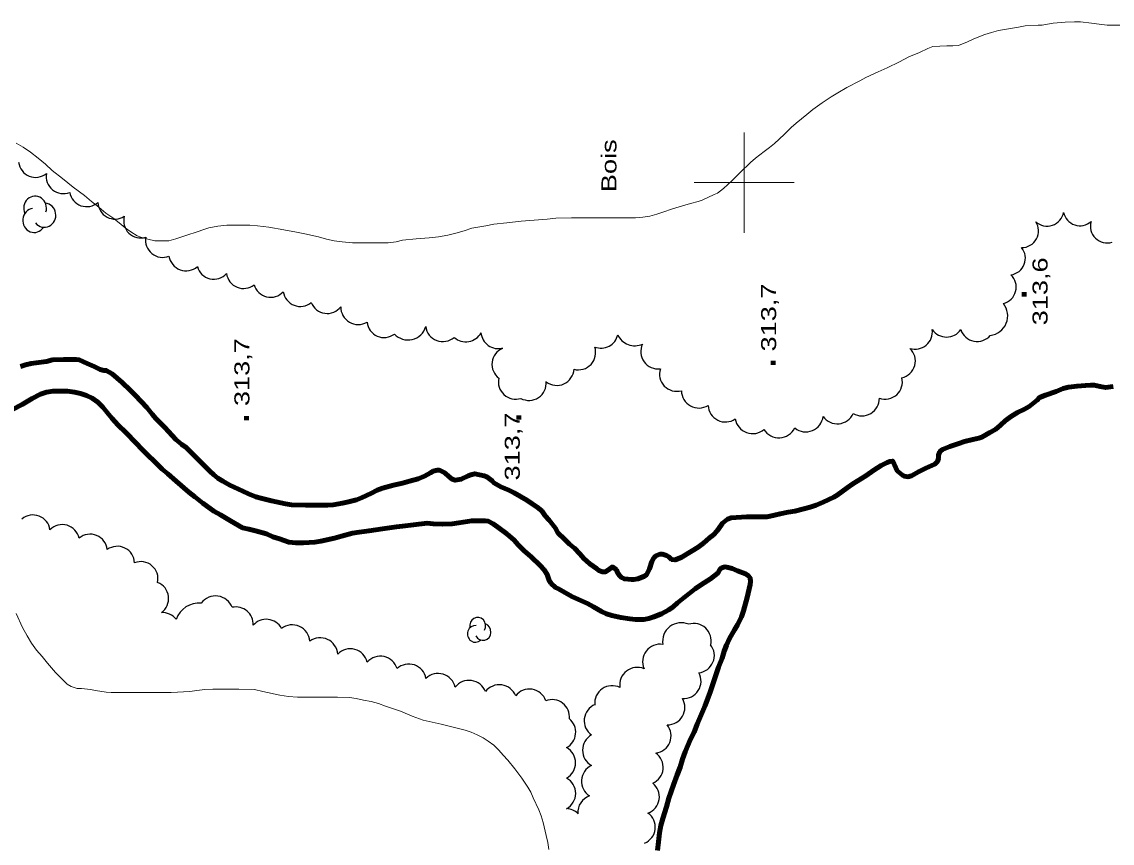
# Model space of a CAD drawing. Extents: x 240591 to 242335, y 5323482 to 5326937.
# Drawn here: x 241255.7 to 241473.5, y 5324068.1 to 5324232.1 of the extents above; entities that cross this region are included whole.
import ezdxf
from ezdxf.enums import TextEntityAlignment as Align

# ---------------------------------------------------------------- set-up
doc = ezdxf.new("R2010")
doc.units = 0
doc.header["$LTSCALE"] = 1.2
doc.linetypes.add('DASH_DOUBLE_DOT', pattern=[9.2, 5, -1.2, 0.3, -1.2, 0.3, -1.2])
doc.linetypes.add('LONG_DASHED', pattern=[7.5, 6, -1.5])
for name, color, linetype, lineweight in [('2', 7, 'Continuous', 13), ('3', 7, 'Continuous', 140), ('4', 7, 'DASH_DOUBLE_DOT', 53), ('44', 7, 'Continuous', 25), ('61', 7, 'Continuous', 13)]:
    doc.layers.add(name, color=color, linetype=linetype, lineweight=lineweight)

msp = doc.modelspace()

# ---------------------------------------------------------------- linework, layer by layer
at = {"layer": '2', "linetype": 'LONG_DASHED'}
for points in [[(241458.7, 5324231.4), (241456.1, 5324231.3), (241454.8, 5324231), (241452.4, 5324230.6), (241450.8, 5324230.4), (241449.4, 5324230), (241448.1, 5324229.6), (241445.9, 5324228.7), (241444.6, 5324228.1), (241442.8, 5324227.4), (241441.7, 5324227.3), (241440.5, 5324227.3), (241437.7, 5324227.2), (241436.7, 5324226.8), (241435, 5324226), (241432.9, 5324225.1), (241431, 5324224.1), (241428.6, 5324222.9), (241426.8, 5324222.1), (241424.3, 5324221), (241423.1, 5324220.3), (241420.5, 5324219), (241418.7, 5324217.9), (241417.4, 5324217.1), (241415.6, 5324215.9), (241413.7, 5324214.6), (241412.5, 5324213.6), (241410.4, 5324211.9), (241409.4, 5324211), (241408, 5324209.6), (241406.1, 5324207.8), (241405.1, 5324207), (241404, 5324206.2), (241402.3, 5324204.9), (241401.3, 5324204), (241399.2, 5324202), (241397.6, 5324200.4), (241395.9, 5324198.8), (241394.7, 5324197.9), (241394, 5324197.6), (241391.6, 5324196.5), (241390.8, 5324196.2), (241389.3, 5324195.8), (241387, 5324195.2), (241385.5, 5324194.7), (241384, 5324194.2), (241382.6, 5324193.7), (241381.2, 5324193.3), (241379.8, 5324193.1), (241378.3, 5324193), (241376.6, 5324193), (241373.7, 5324193), (241370.9, 5324193), (241368.1, 5324193), (241365.5, 5324193), (241362.4, 5324192.9), (241360.7, 5324192.7), (241358.1, 5324192.5), (241355.5, 5324192.3), (241352.6, 5324192), (241350, 5324191.7), (241348.4, 5324191.4), (241345.6, 5324190.9), (241344.1, 5324190.4), (241342.4, 5324189.9), (241340.8, 5324189.5), (241339, 5324189.2), (241337.1, 5324189), (241334.5, 5324188.8), (241331.8, 5324188.5), (241330.5, 5324188.2), (241328.9, 5324188), (241326.9, 5324188), (241324.3, 5324188), (241321.8, 5324188), (241319.7, 5324188.2), (241318.1, 5324188.4), (241316.6, 5324188.7), (241315, 5324189.2), (241312.3, 5324189.8), (241310.6, 5324190.1), (241308.1, 5324190.6), (241305.1, 5324191.1), (241302.8, 5324191.4), (241301.3, 5324191.5), (241299.8, 5324191.5), (241296.7, 5324191.5), (241294.9, 5324191.3), (241293.1, 5324191), (241292.3, 5324190.7), (241290.6, 5324190.1), (241288.9, 5324189.6), (241286.5, 5324188.8), (241285.1, 5324188.4), (241284.4, 5324188.4), (241282.3, 5324188.4), (241280.9, 5324188.7), (241279.5, 5324189.1), (241278.8, 5324189.4), (241277.5, 5324190.2), (241276.4, 5324191)], [(241276.4, 5324191), (241275.2, 5324192), (241273.9, 5324193), (241272.5, 5324193.9), (241271.1, 5324195.1), (241269.7, 5324196.2), (241268.3, 5324197.4), (241266, 5324199.1), (241263.9, 5324200.8), (241261.8, 5324202.4), (241260.5, 5324203.7), (241259, 5324204.9), (241257.5, 5324206.1), (241256, 5324207.1), (241254.6, 5324207.9)], [(241254.6, 5324114), (241255.9, 5324111.2), (241256.8, 5324109.5), (241257.7, 5324108.1), (241258.7, 5324106.7), (241259.8, 5324105.4), (241260.9, 5324104.1), (241262.5, 5324102.2), (241263.7, 5324101), (241264.8, 5324099.9), (241265.6, 5324099.4)], [(241265.6, 5324099.4), (241266.8, 5324099), (241267.7, 5324099), (241269.5, 5324098.8), (241270.5, 5324098.6), (241272.6, 5324098.3), (241273.6, 5324098.2), (241275.7, 5324098.2), (241278.8, 5324098.2), (241282.3, 5324098.2), (241285.6, 5324098.2), (241289.3, 5324098.4), (241290.7, 5324098.6), (241292.3, 5324098.8), (241293.9, 5324098.9), (241295.7, 5324098.9), (241299.1, 5324098.9), (241302.2, 5324098.8), (241303.9, 5324098.4), (241307.3, 5324097.7), (241309, 5324097.4), (241310.8, 5324097.3), (241312.5, 5324097.3), (241315.3, 5324097.3), (241318.8, 5324097.3), (241321.2, 5324097.2), (241322.5, 5324097), (241324, 5324096.7), (241325.5, 5324096.4), (241327, 5324096), (241328.4, 5324095.5), (241330.8, 5324094.7), (241331.4, 5324094.5), (241333.7, 5324093.5), (241335.9, 5324092.7), (241337.1, 5324092.4), (241339.5, 5324091.9), (241341.9, 5324091.3), (241344.3, 5324090.7), (241345.5, 5324090.3), (241346.7, 5324089.8), (241347.9, 5324089.2), (241348.9, 5324088.5), (241350, 5324087.7), (241351, 5324086.7), (241351.9, 5324085.7), (241352.8, 5324084.7), (241354.2, 5324083), (241355.6, 5324081.1), (241356.8, 5324079.3), (241357.4, 5324078.3), (241357.9, 5324077.2), (241359, 5324074.8), (241359.5, 5324073.6), (241359.9, 5324072.3), (241360.5, 5324069.7), (241360.8, 5324068.3), (241361, 5324066.9)]]:
    msp.add_lwpolyline(points, dxfattribs=at)
at = {"layer": '2'}
msp.add_lwpolyline([(241475.6, 5324231.4), (241472.5, 5324231.4), (241470.9, 5324231.6), (241469.4, 5324231.8), (241467.2, 5324232.1), (241466, 5324232.1), (241464.1, 5324232), (241461.7, 5324231.8), (241460.6, 5324231.6), (241459.5, 5324231.4), (241458.7, 5324231.4)], dxfattribs=at)
at = {"layer": '3'}
for p, q in [((241455.9, 5324177.3), (241455.9, 5324178.1)), ((241405.8, 5324163.6), (241405.8, 5324164.4)), ((241300.6, 5324152.6), (241300.6, 5324153.4)), ((241355, 5324152.7), (241355, 5324153.5))]:
    msp.add_line(p, q, dxfattribs=at)
at = {"layer": '4', "linetype": 'Continuous', "lineweight": 90}
for points in [[(241280.7, 5324155.1), (241279.6, 5324156.3), (241278.4, 5324157.6), (241277.4, 5324158.6), (241275.8, 5324160.1), (241273.8, 5324161.8), (241272.6, 5324162.5), (241272.1, 5324162.5), (241271.4, 5324162.7), (241270.2, 5324163.3), (241268.8, 5324163.9), (241267.2, 5324164.6), (241266.6, 5324164.7), (241264.1, 5324164.7), (241261.9, 5324164.6), (241260.7, 5324164.3), (241258.6, 5324164), (241257.6, 5324163.9), (241256.5, 5324163.6), (241255.5, 5324163.3)], [(241253.9, 5324154.7), (241255.8, 5324155.7), (241257.8, 5324156.9), (241259.5, 5324157.8), (241260.7, 5324158.2), (241262, 5324158.4), (241263.4, 5324158.4), (241264.9, 5324158.4), (241266.3, 5324158.2), (241267.5, 5324157.9), (241268.7, 5324157.5), (241269.8, 5324157), (241270.9, 5324156.2), (241271.9, 5324155.2), (241272.8, 5324154.1), (241273.7, 5324153), (241275, 5324151.6), (241276.5, 5324150.1), (241278.6, 5324148), (241279.7, 5324146.8), (241280.8, 5324145.7), (241282.4, 5324144.2), (241283.8, 5324142.8), (241284.9, 5324141.9), (241286.6, 5324140.4), (241289.1, 5324138.2), (241290.3, 5324137.3), (241291.9, 5324136), (241294.1, 5324134.4), (241295.4, 5324133.7), (241297.4, 5324132.5), (241299.8, 5324131.1), (241301.1, 5324130.8), (241302.4, 5324130.5), (241304.6, 5324129.9), (241305.9, 5324129.3), (241307.2, 5324128.9), (241309.1, 5324128.2), (241310.5, 5324128.1), (241312, 5324128.1), (241314.3, 5324128.2), (241315.5, 5324128.4), (241318.2, 5324129), (241319.6, 5324129.4), (241321.8, 5324130), (241323.1, 5324130.2), (241325.1, 5324130.5), (241327.8, 5324130.9), (241330.6, 5324131.3), (241331.8, 5324131.4), (241334, 5324131.7), (241336.7, 5324132), (241337.9, 5324131.9), (241339.8, 5324131.8), (241341.7, 5324131.9), (241343, 5324132.1), (241345.6, 5324132.5), (241346.7, 5324132.5), (241348.3, 5324132.5), (241348.9, 5324132.4), (241349.9, 5324131.9), (241350.8, 5324131.2), (241352.6, 5324129.9), (241354.1, 5324128.6), (241354.9, 5324127.7), (241356.1, 5324126.5), (241357.5, 5324125.3), (241359.3, 5324123.6), (241360.1, 5324122.7), (241360.7, 5324121.8), (241361.1, 5324120.6), (241361.5, 5324120)], [(241473.7, 5324159.3), (241472.2, 5324159.1), (241471.1, 5324159.3), (241469.9, 5324159.6), (241469.2, 5324159.6), (241468.2, 5324159.5), (241466.5, 5324159.4), (241464.8, 5324159.2), (241463.7, 5324158.9), (241462.3, 5324158.3), (241460.2, 5324157.6), (241459, 5324157.1), (241458.5, 5324156.6), (241456.9, 5324155.3), (241456, 5324154.8), (241454.6, 5324154.1), (241453.4, 5324153.4), (241452.2, 5324152.5), (241451.2, 5324151.6), (241450.2, 5324150.7), (241449.1, 5324150.1), (241447.5, 5324149.2), (241446.9, 5324149), (241445.7, 5324148.7), (241444, 5324148.3), (241442.9, 5324147.9), (241441.1, 5324147.3), (241439.6, 5324146.7), (241439.1, 5324146.3), (241438.8, 5324145.6), (241438.8, 5324144.9), (241438.6, 5324144.3), (241438.1, 5324143.8), (241437.5, 5324143.5), (241436.3, 5324143), (241434.8, 5324142.3), (241433.4, 5324141.5), (241432.7, 5324141.3), (241432, 5324141.4), (241431.6, 5324141.6), (241430.6, 5324142.5), (241430.3, 5324143.1), (241429.7, 5324144.4), (241429.1, 5324144.3), (241428.6, 5324144.1), (241427.4, 5324143.5), (241425.9, 5324142.6), (241424.3, 5324141.5), (241421.7, 5324139.9), (241420.6, 5324139.1), (241418.6, 5324137.6), (241417.9, 5324137.2), (241415.8, 5324136.2), (241414.4, 5324135.6), (241413.2, 5324135.2), (241411.9, 5324134.9), (241410.1, 5324134.4), (241408.8, 5324134.2), (241407.2, 5324133.9), (241406.1, 5324133.6), (241404.6, 5324133.3), (241403.5, 5324133.3), (241400.5, 5324133.3), (241397.4, 5324133.1), (241396.7, 5324132.8), (241395.7, 5324132), (241395.4, 5324131.6), (241394.6, 5324130.5), (241393.9, 5324129.7), (241393.1, 5324129.1), (241391.9, 5324128)], [(241391.9, 5324128), (241390.8, 5324127.2), (241389.6, 5324126.5), (241387.4, 5324125.2), (241386.2, 5324124.7), (241385.5, 5324124.8), (241385, 5324125.3), (241384.5, 5324125.6), (241383.7, 5324125.8), (241383.2, 5324125.8), (241382.4, 5324125.5), (241382, 5324125.1), (241381.6, 5324124.4), (241381.1, 5324122.9), (241380.5, 5324121.7), (241380, 5324121.4), (241378.8, 5324120.9), (241378, 5324120.8), (241377.5, 5324120.8), (241376.1, 5324120.9), (241375.5, 5324121.2), (241375.1, 5324121.6), (241374.7, 5324122.2), (241374.5, 5324122.7), (241373.7, 5324123.3), (241373.2, 5324122.9), (241372.3, 5324122.3), (241371.7, 5324122.3), (241371, 5324122.6), (241370.5, 5324123), (241369.2, 5324123.9), (241368, 5324125), (241367.2, 5324125.9), (241366.1, 5324127), (241365.1, 5324127.8), (241364.1, 5324128.8), (241362.8, 5324130.1), (241362.3, 5324131), (241361.1, 5324132.6), (241360.3, 5324133.5), (241359.6, 5324134.5), (241358.7, 5324135.2), (241357.7, 5324135.9), (241356.6, 5324136.6), (241354.1, 5324138.1), (241353, 5324138.6), (241351.4, 5324139.3), (241350, 5324140.1), (241349.7, 5324140.5), (241348.6, 5324141.3), (241348.1, 5324141.5), (241346.2, 5324141.9), (241345.4, 5324141.7), (241344.9, 5324141.5), (241343.5, 5324140.8), (241342.3, 5324140.6), (241341.7, 5324140.8), (241341.1, 5324141.3), (241340.2, 5324142.1), (241339.2, 5324142.6), (241338.7, 5324142.6), (241337.9, 5324142.4), (241337.4, 5324142.1), (241336.2, 5324141.4), (241334.9, 5324140.9), (241333.2, 5324140.4), (241331.8, 5324140), (241330, 5324139.6), (241327.8, 5324139), (241326.7, 5324138.6), (241325.6, 5324138), (241323.6, 5324137.1), (241322.6, 5324136.7), (241321, 5324136.3), (241319.8, 5324136), (241317.9, 5324135.7), (241316.8, 5324135.6), (241315, 5324135.6), (241312.4, 5324135.6), (241309.6, 5324135.7), (241308.4, 5324135.9), (241305.6, 5324136.5), (241303.5, 5324137), (241302.5, 5324137.3), (241301, 5324137.9), (241299.9, 5324138.4), (241297.3, 5324139.6), (241295.9, 5324140.4), (241294.9, 5324141), (241294.1, 5324141.7), (241293.3, 5324142.4), (241291.4, 5324144.3), (241289.9, 5324145.8), (241288.6, 5324147.1), (241287.7, 5324147.7), (241286.5, 5324148.7), (241285.8, 5324149.5), (241284.3, 5324151.1), (241282.5, 5324152.9), (241281.8, 5324153.8), (241280.7, 5324155.1)], [(241361.5, 5324120), (241362.3, 5324119.2), (241362.9, 5324118.9), (241365.6, 5324117.4), (241366.9, 5324116.8), (241368.7, 5324116), (241369.9, 5324115.3), (241371.5, 5324114.4), (241372.5, 5324113.9), (241373.6, 5324113.6), (241375.4, 5324113.2), (241377.2, 5324112.9), (241378.3, 5324112.8), (241380, 5324112.8), (241381, 5324113), (241382, 5324113.3), (241383.5, 5324113.9), (241385, 5324114.7), (241385.8, 5324115.3), (241386.7, 5324116.1), (241388, 5324117.2), (241390.2, 5324118.9), (241391.5, 5324119.8), (241393.3, 5324120.9), (241394.8, 5324122.1), (241395.1, 5324122.7), (241395.5, 5324123.1), (241396.2, 5324123.3), (241396.8, 5324123.2), (241397.6, 5324123), (241398.7, 5324122.5), (241400.3, 5324121.9), (241400.9, 5324121.5), (241401.2, 5324121.1), (241401.3, 5324120.4), (241401.2, 5324119.8), (241400.6, 5324117.2), (241399.9, 5324114.5), (241399.5, 5324113.3), (241398.7, 5324111.7), (241398.1, 5324110.7), (241397.1, 5324109), (241396.5, 5324107.7), (241396, 5324106.5), (241395.6, 5324105.1), (241394.9, 5324103.3), (241394.2, 5324101.3), (241393.2, 5324098.3), (241392.2, 5324095.6), (241391.6, 5324094.2), (241390.6, 5324091.9), (241390, 5324090.3), (241389.3, 5324088.9), (241388.2, 5324086.4), (241387.7, 5324084.9), (241387.2, 5324083.3), (241386.6, 5324081.8), (241385.9, 5324079.8), (241385, 5324077.1), (241384.5, 5324075.4), (241383.8, 5324073.1), (241383.4, 5324071.7), (241383.1, 5324070.2), (241382.9, 5324068.4), (241382.7, 5324066.7)]]:
    msp.add_lwpolyline(points, dxfattribs=at)
at = {"layer": '44'}
for centre, radius, start, end in [((241264.033, 5324201.234), 3.425, 169.97722, 292.07617), ((241288.558, 5324185.855), 3.459, 188.90182, 310.62973), ((241294.112, 5324184.157), 3.429, 195.6757, 317.50387), ((241300.012, 5324182.261), 3.398, 187.11779, 308.99283), ((241305.45, 5324180.542), 3.426, 195.60395, 317.34502), ((241311.355, 5324178.703), 3.42, 188.11176, 309.92335), ((241371.395, 5324170.429), 3.472, 249.34075, 346.90329), ((241257.972, 5324130.219), 3.443, 8.19218, 130.18356), ((241263.827, 5324128.263), 3.461, 12.98021, 134.99901), ((241387.461, 5324108.405), 3.745, 66.90603, 188.82859), ((241321.333, 5324103.451), 3.495, 13.56162, 135.50056), ((241383.242, 5324104.357), 3.512, 81.51302, 203.44082), ((241327.353, 5324101.969), 3.489, 17.00747, 138.7505), ((241362.898, 5324090.285), 3.473, 298.40929, 50.48077), ((241362.906, 5324078.08), 3.465, 298.32356, 61.67644), ((241379.611, 5324077.401), 3.461, 290.08751, 52.04596), ((241370.26, 5324074.284), 3.469, 109.19015, 184.23591)]:
    msp.add_arc(centre, radius, start, end, dxfattribs=at)
for centre, major_axis, ratio, start_param, end_param in [((241258.494, 5324204.449), (3.153, -1.271), 0.998987, 3.6385388, 5.7862391), ((241268.695, 5324198.625), (2.585, 2.242), 0.999983, 2.5929826, 4.7215508), ((241258.404, 5324194.87), (0.002, 2.42), 0.941541, 4.405599, 8.2921743), ((241260.267, 5324193.498), (0.002, 2.42), 0.941541, 2.2619595, 6.2009685), ((241274.359, 5324196.126), (-1.59, -3.005), 0.999994, 5.2182976, 7.3488781), ((241258.223, 5324192.457), (0.002, 2.42), 0.941541, 0.1353421, 4.1052172), ((241279.524, 5324192.372), (-2.394, -2.452), 0.999911, 5.2175453, 7.3484104), ((241460.507, 5324194.676), (1.698, -2.889), 0.999708, 5.0127338, 7.1373967), ((241467.07, 5324194.738), (3.133, -1.163), 0.999984, 3.7018008, 5.7943491), ((241455.438, 5324190.38), (1.613, 2.936), 0.999935, 3.6356782, 5.7890997), ((241472.5, 5324191.307), (2.392, -2.335), 0.999936, 3.6322129, 5.792565), ((241283.873, 5324188.492), (3.377, -0.513), 0.999995, 3.1164055, 5.2434041), ((241452.845, 5324184.903), (3.105, -1.213), 0.999524, 5.2186601, 7.3480598), ((241450.947, 5324179.146), (3.283, -0.855), 0.999977, 5.2181437, 7.3464127), ((241316.743, 5324177.289), (-0.495, -3.378), 0.999994, 5.2197396, 7.3486589), ((241448.712, 5324173.414), (3.64, -1.489), 0.999488, 5.2171648, 7.3432069), ((241322.93, 5324175.133), (-2.195, -2.69), 0.999832, 5.3716629, 7.4993297), ((241328.089, 5324172.49), (-1.811, -2.898), 0.999826, 5.3733671, 7.4967366), ((241332.876, 5324172.259), (0.856, -3.569), 0.999956, 5.2187721, 7.345707), ((241339.833, 5324171.723), (3.228, -1.227), 0.999939, 3.6367058, 5.7880722), ((241344.421, 5324171.672), (3.271, 1.136), 0.999985, 3.6398765, 5.4580113), ((241350.881, 5324170.305), (2.375, -2.489), 0.999864, 4.0284022, 5.7928093), ((241378.163, 5324171.125), (-2.191, -2.986), 0.999881, 5.7581179, 7.3472151), ((241434.158, 5324170.201), (3.27, -1.094), 0.999862, 4.7325792, 6.7410005), ((241440.42, 5324172.613), (3.43, -0.364), 0.999939, 3.847447, 5.7905355), ((241446.541, 5324171.722), (-0.659, -3.372), 0.999912, 5.2164827, 7.3475617), ((241366.91, 5324166.07), (2.349, 2.519), 0.999939, 3.6337995, 5.7909785), ((241382.819, 5324166.262), (2.022, -2.798), 0.999862, 3.6377093, 5.7870687), ((241353.092, 5324163.724), (-0.327, -3.433), 0.999863, 3.6362585, 5.7352819), ((241430.746, 5324164.415), (0.919, 3.326), 0.999864, 3.6345146, 5.7902634), ((241362.594, 5324162.974), (1.279, -3.202), 0.99861, 5.248914, 7.4065043), ((241386.54, 5324161.778), (2.386, -2.476), 0.999864, 3.6316426, 5.7931354), ((241354.378, 5324160.221), (3.441, 0.257), 0.999653, 2.8492031, 4.9418007), ((241428.162, 5324160.23), (1.92, -2.868), 0.998583, 5.3517879, 7.5045386), ((241357.028, 5324159.984), (2.879, 1.912), 0.999985, 3.6390593, 5.7857187), ((241390.96, 5324158.478), (-1.679, -3.048), 0.999995, 5.2181767, 7.3472134), ((241423.536, 5324156.922), (1.55, -3.112), 0.999147, 5.2871917, 7.4088317), ((241396.281, 5324155.69), (-1.55, -3.11), 0.999805, 5.220743, 7.3445923), ((241401.68, 5324153.375), (-1.189, -3.275), 0.999995, 5.2206386, 7.3447761), ((241412.315, 5324153.741), (1.329, -3.229), 0.999094, 5.2158524, 7.3461362), ((241418.608, 5324155.301), (0.341, -3.431), 0.999553, 5.2217943, 7.3460314), ((241406.967, 5324152.604), (0.166, -3.534), 0.999979, 5.2203833, 7.342833), ((241269.391, 5324126.392), (-3.182, 1.299), 0.999756, 3.6335761, 5.7912019), ((241274.829, 5324123.972), (-2.189, 2.647), 0.999716, 4.0618665, 6.2206919), ((241279.508, 5324120.898), (-2.628, 2.229), 0.999754, 3.6383228, 5.7864551), ((241281.639, 5324116.983), (-0.426, 3.412), 0.999939, 3.6348987, 5.7898791), ((241294.445, 5324113.939), (0.485, 3.521), 0.999917, 5.2180372, 7.3478506), ((241291.244, 5324111.078), (-4.196, 2.729), 0.999684, 5.2178465, 6.503757), ((241298.498, 5324111.835), (-2.25, 2.635), 0.99994, 3.9535956, 5.7913125), ((241283.816, 5324110.736), (-1.806, 2.939), 0.999862, 4.813148, 5.7861153), ((241304.56, 5324109.366), (-2.954, 1.81), 0.999921, 4.1857083, 6.1117632), ((241346.791, 5324111.53), (0.001, 1.679), 0.941542, 4.1867133, 8.0732886), ((241309.744, 5324108.162), (1.458, 3.247), 0.999917, 5.2210895, 7.3484763), ((241346.326, 5324109.925), (0.001, 1.679), 0.941542, 6.1996418, 10.1695169), ((241347.858, 5324110.303), (0.001, 1.679), 0.941542, 2.0430738, 5.9820828), ((241389.962, 5324108.545), (-2.476, 2.42), 0.99994, 3.6799382, 5.788952), ((241315.351, 5324105.642), (1.468, 3.178), 0.999231, 5.2183614, 7.3458863), ((241390.591, 5324105.602), (1.294, 3.212), 0.999985, 3.6343416, 5.7605313), ((241333.04, 5324100.415), (1.105, 3.306), 0.999995, 5.2152335, 7.3456387), ((241338.892, 5324098.531), (1.003, 3.341), 0.999736, 5.2175873, 7.3427171), ((241378.657, 5324099.739), (-2.146, 2.761), 0.999979, 5.2220407, 7.3451065), ((241387.894, 5324100.493), (2.73, -2.19), 0.999696, 5.3302336, 7.4560908), ((241345.076, 5324097.157), (0.504, 3.453), 0.999807, 5.2184883, 7.3486106), ((241351.123, 5324096.282), (0.487, 3.458), 0.999807, 5.2207301, 7.3458691), ((241373.636, 5324096.122), (-2.839, -1.979), 0.99994, 3.6348845, 5.7898933), ((241357.128, 5324095.44), (-1.963, 2.848), 0.999742, 4.4390664, 6.5981207), ((241361.655, 5324093.328), (-2.638, 2.25), 0.99994, 3.740961, 5.7888916), ((241371.521, 5324092.586), (-3.418, -0.571), 0.999964, 4.9233925, 7.0762533), ((241384.707, 5324095.229), (2.817, -2.027), 0.999603, 5.3197377, 7.4429276), ((241381.944, 5324089.573), (-2.165, 2.723), 0.999984, 2.5926429, 4.720375), ((241371.237, 5324086.7), (-3.485, 0.283), 0.999404, 5.3031712, 7.425026), ((241362.845, 5324084.18), (3.495, 0), 0.999737, 5.2219742, 7.3443963), ((241380.396, 5324083.3), (3.299, -0.987), 0.999884, 5.4042571, 7.5341083), ((241371.01, 5324080.492), (-3.48, 0.242), 0.999866, 5.2201562, 7.3508209), ((241364.387, 5324071.572), (2.638, 2.245), 0.998952, 0.0836961, 0.8190747), ((241378.789, 5324071.332), (3.135, -1.47), 0.999962, 5.5485015, 7.6725344)]:
    msp.add_ellipse(centre, major_axis=major_axis, ratio=ratio, start_param=start_param, end_param=end_param, dxfattribs=at)
at = {"layer": '61'}
for points in [[(241400, 5324210), (241400, 5324200), (241400, 5324190)], [(241390, 5324200), (241400, 5324200), (241410, 5324200)]]:
    msp.add_lwpolyline(points, dxfattribs=at)

# ---------------------------------------------------------------- texts
at = {"layer": '3', "width": 1.35}
msp.add_text('313,6', height=3, rotation=90, dxfattribs=at).set_placement((241460.6, 5324178.3), align=Align.CENTER)
for p in [(241406.4, 5324166.3), (241301.2, 5324155.4)]:
    msp.add_text('313,7', height=3, rotation=90, dxfattribs=at).set_placement(p)
msp.add_text('313,7', height=3, rotation=90, dxfattribs=at).set_placement((241355.2, 5324154.1), align=Align.RIGHT)
at = {"layer": '44', "width": 1.35}
msp.add_text('Bois', height=3, rotation=90, dxfattribs=at).set_placement((241374.5, 5324198.1))

doc.saveas('drawing.dxf')
